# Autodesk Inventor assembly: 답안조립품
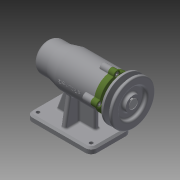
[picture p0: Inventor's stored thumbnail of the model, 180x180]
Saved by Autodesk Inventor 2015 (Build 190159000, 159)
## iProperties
Created: 2019-07
Part Number: 답안조립품
Document SubType Name: Assembly
Designer: now060
Author: now060
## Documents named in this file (12)
- C:\Users\now060\Desktop\파일여기있어요.바탕화면에 폴더만들지 말아주세요.파일저장은 네이버 클라우드에 저장해주세요\왕혜원\490704V1028\답안조립품.iam
- C:\Users\now060\Desktop\파일여기있어요.바탕화면에 폴더만들지 말아주세요.파일저장은 네이버 클라우드에 저장해주세요\왕혜원\490704V1028\V벨트풀리.ipt
- C:\Users\now060\Desktop\파일여기있어요.바탕화면에 폴더만들지 말아주세요.파일저장은 네이버 클라우드에 저장해주세요\왕혜원\490704V1028\멈춤나사 M3.ipt
- C:\Users\now060\Desktop\파일여기있어요.바탕화면에 폴더만들지 말아주세요.파일저장은 네이버 클라우드에 저장해주세요\왕혜원\490704V1028\베어링 6004.ipt
- C:\Users\now060\Desktop\파일여기있어요.바탕화면에 폴더만들지 말아주세요.파일저장은 네이버 클라우드에 저장해주세요\왕혜원\490704V1028\베어링 51202.ipt
- C:\Users\now060\Desktop\파일여기있어요.바탕화면에 폴더만들지 말아주세요.파일저장은 네이버 클라우드에 저장해주세요\왕혜원\490704V1028\본체.ipt
- C:\Users\now060\Desktop\파일여기있어요.바탕화면에 폴더만들지 말아주세요.파일저장은 네이버 클라우드에 저장해주세요\왕혜원\490704V1028\볼트 M4.ipt
- C:\Users\now060\Desktop\파일여기있어요.바탕화면에 폴더만들지 말아주세요.파일저장은 네이버 클라우드에 저장해주세요\왕혜원\490704V1028\어댑터슬리브.ipt
- C:\Users\now060\Desktop\파일여기있어요.바탕화면에 폴더만들지 말아주세요.파일저장은 네이버 클라우드에 저장해주세요\왕혜원\490704V1028\오일 실.ipt
- C:\Users\now060\Desktop\파일여기있어요.바탕화면에 폴더만들지 말아주세요.파일저장은 네이버 클라우드에 저장해주세요\왕혜원\490704V1028\축.ipt
- C:\Users\now060\Desktop\파일여기있어요.바탕화면에 폴더만들지 말아주세요.파일저장은 네이버 클라우드에 저장해주세요\왕혜원\490704V1028\커버.ipt
- C:\Users\now060\Desktop\파일여기있어요.바탕화면에 폴더만들지 말아주세요.파일저장은 네이버 클라우드에 저장해주세요\왕혜원\490704V1028\키 5 x 5 x 16.ipt
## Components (1 placed, 1 different names)
1. V벨트풀리:1
